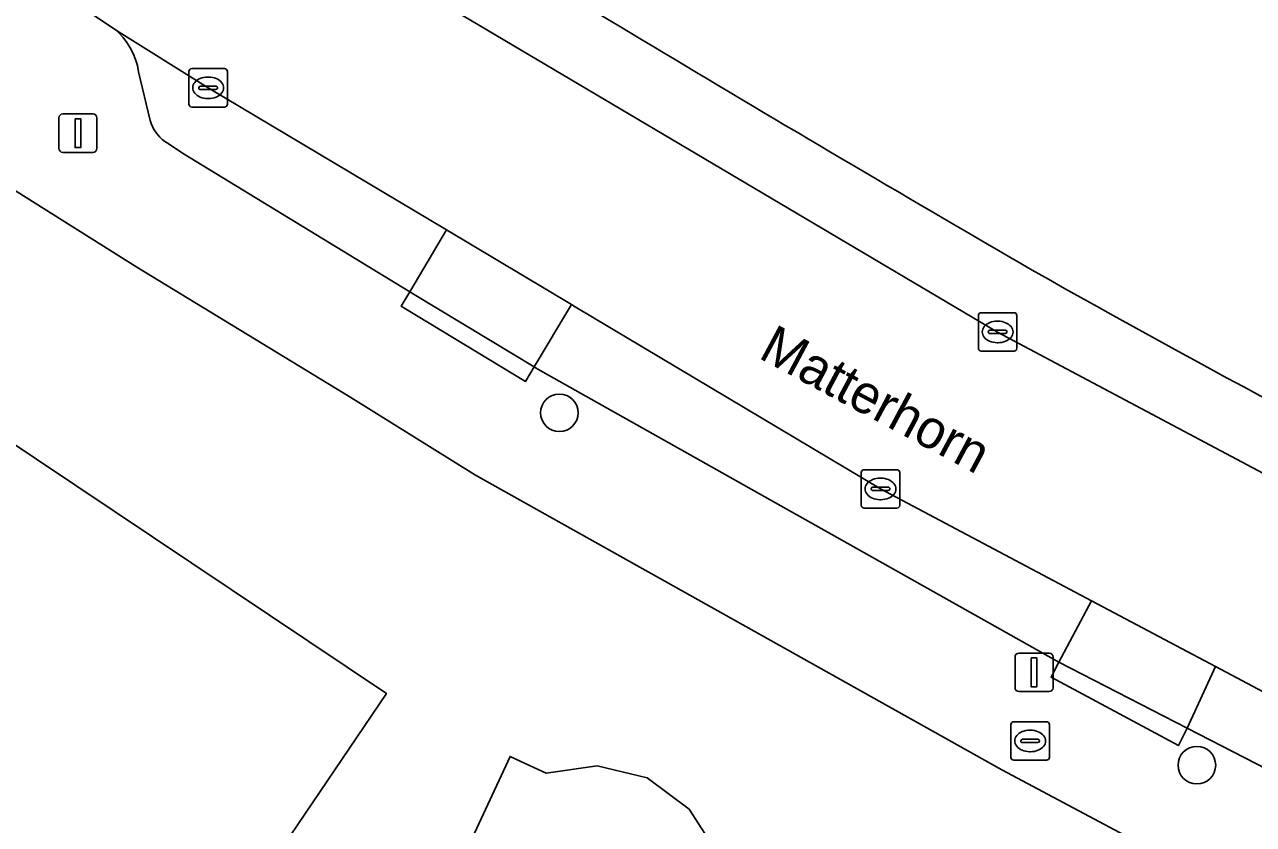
# Model space of a CAD drawing. Extents: x 158835 to 160077, y 386387 to 387778.
# Drawn here: x 159322.29 to 159354.26, y 386620.94 to 386641.75 of the extents above; entities that cross this region are included whole.
import ezdxf

# ---------------------------------------------------------------- set-up
doc = ezdxf.new("R2010")
doc.units = 0
for name, color, linetype in [('IMGEO_Boom', 7, 'Continuous'), ('IMGEO_Brandkraan', 7, 'Continuous'), ('IMGEO_Erf', 7, 'Continuous'), ('IMGEO_Kolk', 7, 'Continuous'), ('IMGEO_Lichtmast', 7, 'Continuous'), ('IMGEO_Openbare_ruimte_label', 7, 'Continuous'), ('IMGEO_Pand', 7, 'Continuous'), ('IMGEO_Parkeervlak_open', 7, 'Continuous'), ('IMGEO_Rijbaan_lokaal_gesloten', 7, 'Continuous'), ('IMGEO_Voetpad_open', 7, 'Continuous')]:
    doc.layers.add(name, color=color, linetype=linetype)

msp = doc.modelspace()

# ---------------------------------------------------------------- linework, layer by layer
at = {"layer": 'IMGEO_Boom'}
for centre in [(159336.201, 386631.65), (159352.786, 386622.485)]:
    msp.add_circle(centre, 0.489, dxfattribs=at)
at = {"layer": 'IMGEO_Brandkraan'}
for p, q in [((159347.947, 386622.688), (159347.947, 386623.54)), ((159348.022, 386623.614), (159348.874, 386623.614)), ((159348.948, 386623.54), (159348.948, 386622.688)), ((159348.206, 386623.108), (159348.206, 386623.12)), ((159348.249, 386623.157), (159348.647, 386623.157)), ((159348.435, 386623.394), (159348.46, 386623.394)), ((159348.69, 386623.12), (159348.69, 386623.108)), ((159348.644, 386623.071), (159348.246, 386623.071)), ((159348.458, 386622.834), (159348.433, 386622.834)), ((159348.874, 386622.614), (159348.022, 386622.614))]:
    msp.add_line(p, q, dxfattribs=at)
for points in [[(159347.947, 386622.688), (159347.947, 386623.54)], [(159348.022, 386623.614), (159348.874, 386623.614)], [(159348.948, 386623.54), (159348.948, 386622.688)], [(159348.874, 386622.614), (159348.022, 386622.614)]]:
    msp.add_lwpolyline(points, dxfattribs=at)
for centre, radius, start, end in [((159348.024, 386623.538), 0.0765, 91.552, 178.448), ((159348.024, 386623.538), 0.0765, 91.552, 178.448), ((159348.872, 386623.538), 0.0765, 1.552, 88.448), ((159348.872, 386623.538), 0.0765, 1.552, 88.448), ((159348.246, 386623.117), 0.0403, 85.8775, 175.7526), ((159348.651, 386623.119), 0.0386, 1.7309, 96.639), ((159348.243, 386623.107), 0.0366, 178.938, 274.7102), ((159348.647, 386623.114), 0.043, 264.8664, 352.4533), ((159348.024, 386622.69), 0.0765, 181.552, 268.448), ((159348.024, 386622.69), 0.0765, 181.552, 268.448), ((159348.872, 386622.69), 0.0765, 271.552, 358.448), ((159348.872, 386622.69), 0.0765, 271.552, 358.448)]:
    msp.add_arc(centre, radius, start, end, dxfattribs=at)
for centre, major_axis, ratio, start_param, end_param in [((159348.434, 386623.114), (-0.387, 0.002), 0.722429, 4.712389, 7.853982), ((159348.459, 386623.114), (-0.39, 0.002), 0.717154, 1.570796, 4.712389)]:
    msp.add_ellipse(centre, major_axis=major_axis, ratio=ratio, start_param=start_param, end_param=end_param, dxfattribs=at)
at = {"layer": 'IMGEO_Erf'}
for points in [[(159426.262, 386590.078), (159425.471, 386590.29), (159424.673, 386590.43), (159422.846, 386590.766), (159421.294, 386591.006), (159420.138, 386591.222), (159418.758, 386591.64), (159417.314, 386592.1), (159409.486, 386594.837), (159405.916, 386596.132), (159403.97, 386596.822), (159400.475, 386598.135), (159386.22, 386603.858), (159382.649, 386605.402), (159367.084, 386612.517), (159363.661, 386614.16), (159351.051, 386620.582), (159347.709, 386622.366), (159334.021, 386630.024), (159330.778, 386632.045), (159325.211, 386635.435), (159320.616, 386638.324)], [(159329.986, 386612.103), (159334.918, 386622.713), (159335.31, 386622.531), (159335.861, 386622.275), (159337.184, 386622.464), (159338.486, 386622.151), (159339.578, 386621.338), (159340.316, 386620.2)]]:
    msp.add_lwpolyline(points, dxfattribs=at)
msp.add_lwpolyline([(159326.892, 386617.237), (159326.589, 386616.789), (159323.922, 386618.593), (159324.22, 386619.033), (159321.202, 386621.061), (159313.402, 386609.64), (159309.341, 386611.541), (159309.249, 386611.591), (159310.962, 386614.093), (159310.479, 386614.408), (159312.402, 386617.249), (159311.925, 386617.552), (159313.862, 386620.39), (159313.389, 386620.699), (159315.32, 386623.54), (159314.84, 386623.851), (159316.431, 386626.201), (159316.933, 386626.939), (159317.487, 386626.563), (159318.424, 386627.943), (159317.106, 386628.824), (159317.252, 386629.043), (159319.546, 386632.48), (159331.703, 386624.349)], close=True, dxfattribs=at)
for centre, radius, start, end in [((159790.309, 387395.826), 879.49, 238.436929, 239.84473), ((159511.952, 386925.067), 332.636, 240.56851, 243.23292)]:
    msp.add_arc(centre, radius, start, end, dxfattribs=at)
at = {"layer": 'IMGEO_Kolk'}
for p, q in [((159326.563, 386639.677), (159326.563, 386640.529)), ((159326.638, 386640.603), (159327.49, 386640.603)), ((159327.051, 386640.383), (159327.076, 386640.383)), ((159327.564, 386640.529), (159327.564, 386639.677)), ((159326.822, 386640.097), (159326.822, 386640.109)), ((159327.26, 386640.06), (159326.862, 386640.06)), ((159326.865, 386640.146), (159327.263, 386640.146)), ((159327.306, 386640.109), (159327.306, 386640.097)), ((159327.074, 386639.823), (159327.049, 386639.823)), ((159327.49, 386639.603), (159326.638, 386639.603)), ((159347.101, 386633.327), (159347.101, 386634.179)), ((159347.176, 386634.253), (159348.028, 386634.253)), ((159347.589, 386634.033), (159347.614, 386634.033)), ((159348.102, 386634.179), (159348.102, 386633.327)), ((159347.36, 386633.747), (159347.36, 386633.759)), ((159347.798, 386633.71), (159347.4, 386633.71)), ((159347.403, 386633.796), (159347.801, 386633.796)), ((159347.844, 386633.759), (159347.844, 386633.747)), ((159347.612, 386633.473), (159347.587, 386633.473)), ((159348.028, 386633.253), (159347.176, 386633.253)), ((159344.13, 386630.17), (159344.982, 386630.17)), ((159344.055, 386629.244), (159344.055, 386630.096)), ((159344.543, 386629.95), (159344.568, 386629.95)), ((159345.056, 386630.096), (159345.056, 386629.244)), ((159344.314, 386629.664), (159344.314, 386629.676)), ((159344.752, 386629.627), (159344.354, 386629.627)), ((159344.357, 386629.713), (159344.755, 386629.713)), ((159344.798, 386629.676), (159344.798, 386629.664)), ((159344.566, 386629.39), (159344.541, 386629.39)), ((159344.982, 386629.17), (159344.13, 386629.17))]:
    msp.add_line(p, q, dxfattribs=at)
for points in [[(159326.563, 386639.677), (159326.563, 386640.529)], [(159326.638, 386640.603), (159327.49, 386640.603)], [(159327.564, 386640.529), (159327.564, 386639.677)], [(159327.49, 386639.603), (159326.638, 386639.603)], [(159347.101, 386633.327), (159347.101, 386634.179)], [(159347.176, 386634.253), (159348.028, 386634.253)], [(159348.102, 386634.179), (159348.102, 386633.327)], [(159348.028, 386633.253), (159347.176, 386633.253)], [(159344.13, 386630.17), (159344.982, 386630.17)], [(159344.055, 386629.244), (159344.055, 386630.096)], [(159345.056, 386630.096), (159345.056, 386629.244)], [(159344.982, 386629.17), (159344.13, 386629.17)]]:
    msp.add_lwpolyline(points, dxfattribs=at)
for centre, radius, start, end in [((159326.64, 386640.527), 0.0765, 91.552, 178.448), ((159326.64, 386640.527), 0.0765, 91.552, 178.448), ((159327.488, 386640.527), 0.0765, 1.552, 88.448), ((159327.488, 386640.527), 0.0765, 1.552, 88.448), ((159326.862, 386640.106), 0.0403, 85.8775, 175.7526), ((159326.859, 386640.096), 0.0366, 178.938, 274.7102), ((159327.263, 386640.103), 0.043, 264.8664, 352.4533), ((159327.267, 386640.108), 0.0386, 1.7309, 96.639), ((159326.64, 386639.679), 0.0765, 181.552, 268.448), ((159326.64, 386639.679), 0.0765, 181.552, 268.448), ((159327.488, 386639.679), 0.0765, 271.552, 358.448), ((159327.488, 386639.679), 0.0765, 271.552, 358.448), ((159347.178, 386634.177), 0.0765, 91.552, 178.448), ((159347.178, 386634.177), 0.0765, 91.552, 178.448), ((159348.026, 386634.177), 0.0765, 1.552, 88.448), ((159348.026, 386634.177), 0.0765, 1.552, 88.448), ((159347.4, 386633.756), 0.0403, 85.8775, 175.7526), ((159347.397, 386633.746), 0.0366, 178.938, 274.7102), ((159347.801, 386633.753), 0.043, 264.8664, 352.4533), ((159347.805, 386633.758), 0.0386, 1.7309, 96.639), ((159347.178, 386633.329), 0.0765, 181.552, 268.448), ((159347.178, 386633.329), 0.0765, 181.552, 268.448), ((159348.026, 386633.329), 0.0765, 271.552, 358.448), ((159348.026, 386633.329), 0.0765, 271.552, 358.448), ((159344.132, 386630.094), 0.0765, 91.552, 178.448), ((159344.132, 386630.094), 0.0765, 91.552, 178.448), ((159344.98, 386630.094), 0.0765, 1.552, 88.448), ((159344.98, 386630.094), 0.0765, 1.552, 88.448), ((159344.354, 386629.673), 0.0403, 85.8775, 175.7526), ((159344.351, 386629.663), 0.0366, 178.938, 274.7102), ((159344.755, 386629.67), 0.043, 264.8664, 352.4533), ((159344.759, 386629.675), 0.0386, 1.7309, 96.639), ((159344.132, 386629.246), 0.0765, 181.552, 268.448), ((159344.132, 386629.246), 0.0765, 181.552, 268.448), ((159344.98, 386629.246), 0.0765, 271.552, 358.448), ((159344.98, 386629.246), 0.0765, 271.552, 358.448)]:
    msp.add_arc(centre, radius, start, end, dxfattribs=at)
for centre, major_axis, ratio, start_param, end_param in [((159327.05, 386640.103), (-0.387, 0.002), 0.722429, 4.712389, 7.853982), ((159327.075, 386640.103), (-0.39, 0.002), 0.717154, 1.570796, 4.712389), ((159347.588, 386633.753), (-0.387, 0.002), 0.722429, 4.712389, 7.853982), ((159347.613, 386633.753), (-0.39, 0.002), 0.717154, 1.570796, 4.712389), ((159344.542, 386629.67), (-0.387, 0.002), 0.722429, 4.712389, 7.853982), ((159344.567, 386629.67), (-0.39, 0.002), 0.717154, 1.570796, 4.712389)]:
    msp.add_ellipse(centre, major_axis=major_axis, ratio=ratio, start_param=start_param, end_param=end_param, dxfattribs=at)
at = {"layer": 'IMGEO_Lichtmast'}
for p, q in [((159323.281, 386639.425), (159324.071, 386639.425)), ((159324.071, 386639.425), (159323.281, 386639.425)), ((159323.181, 386638.525), (159323.181, 386639.325)), ((159323.181, 386639.325), (159323.181, 386638.525)), ((159324.171, 386639.325), (159324.171, 386638.525)), ((159324.171, 386638.525), (159324.171, 386639.325)), ((159324.071, 386638.425), (159323.281, 386638.425)), ((159323.281, 386638.425), (159324.071, 386638.425)), ((159348.154, 386625.398), (159348.944, 386625.398)), ((159348.944, 386625.398), (159348.154, 386625.398)), ((159348.054, 386624.498), (159348.054, 386625.298)), ((159348.054, 386625.298), (159348.054, 386624.498)), ((159349.044, 386625.298), (159349.044, 386624.498)), ((159349.044, 386624.498), (159349.044, 386625.298)), ((159348.944, 386624.398), (159348.154, 386624.398)), ((159348.154, 386624.398), (159348.944, 386624.398))]:
    msp.add_line(p, q, dxfattribs=at)
for points in [[(159323.601, 386639.3), (159323.751, 386639.3), (159323.751, 386638.55), (159323.601, 386638.55), (159323.601, 386639.3)], [(159348.474, 386625.273), (159348.624, 386625.273), (159348.624, 386624.523), (159348.474, 386624.523), (159348.474, 386625.273)]]:
    msp.add_lwpolyline(points, dxfattribs=at)
for centre, start, end in [((159323.281, 386639.325), 90, 180), ((159323.281, 386639.325), 90, 180), ((159324.071, 386639.325), 0, 90), ((159324.071, 386639.325), 360, 90), ((159323.281, 386638.525), 180, 270), ((159323.281, 386638.525), 180, 270), ((159324.071, 386638.525), 270, 0), ((159324.071, 386638.525), 270, 0), ((159348.154, 386625.298), 90, 180), ((159348.154, 386625.298), 90, 180), ((159348.944, 386625.298), 0, 90), ((159348.944, 386625.298), 360, 90), ((159348.154, 386624.498), 180, 270), ((159348.154, 386624.498), 180, 270), ((159348.944, 386624.498), 270, 0), ((159348.944, 386624.498), 270, 0)]:
    msp.add_arc(centre, 0.1, start, end, dxfattribs=at)
at = {"layer": 'IMGEO_Pand'}
msp.add_lwpolyline([(159331.703, 386624.349), (159319.546, 386632.48), (159317.252, 386629.043), (159317.106, 386628.824), (159318.424, 386627.943), (159317.487, 386626.563), (159316.933, 386626.939), (159316.431, 386626.201), (159314.84, 386623.851), (159315.32, 386623.54), (159313.389, 386620.699), (159313.862, 386620.39), (159311.925, 386617.552), (159312.402, 386617.249), (159310.479, 386614.408), (159310.962, 386614.093), (159309.249, 386611.591), (159309.341, 386611.541), (159313.402, 386609.64), (159321.202, 386621.061), (159324.22, 386619.033), (159323.922, 386618.593), (159326.589, 386616.789), (159326.892, 386617.237)], close=True, dxfattribs=at)
msp.add_lwpolyline([(159340.316, 386620.2), (159339.578, 386621.338), (159338.486, 386622.151), (159337.184, 386622.464), (159335.861, 386622.275), (159335.31, 386622.531), (159334.918, 386622.713), (159329.986, 386612.103)], dxfattribs=at)
at = {"layer": 'IMGEO_Parkeervlak_open'}
for points in [[(159333.267, 386636.405), (159327.065, 386640.104), (159324.681, 386641.593), (159324.74, 386641.536), (159324.851, 386641.414), (159324.951, 386641.282), (159325.039, 386641.142), (159325.114, 386640.995), (159325.175, 386640.841), (159325.223, 386640.683), (159325.256, 386640.521), (159325.558, 386639.257), (159325.583, 386639.175), (159325.615, 386639.096), (159325.654, 386639.019), (159325.699, 386638.947), (159325.751, 386638.879), (159325.809, 386638.816), (159325.872, 386638.758), (159325.94, 386638.706), (159326.013, 386638.661), (159326.023, 386638.655), (159326.401, 386638.4), (159332.308, 386634.797)], [(159336.517, 386634.466), (159335.549, 386632.842), (159335.645, 386632.784), (159349.197, 386625.162), (159350.044, 386626.76), (159344.556, 386629.671), (159336.613, 386634.409)], [(159358.412, 386622.321), (159353.27, 386625.049), (159352.531, 386623.447), (159365.054, 386617.003), (159365.882, 386618.722)]]:
    msp.add_lwpolyline(points, close=True, dxfattribs=at)
at = {"layer": 'IMGEO_Rijbaan_lokaal_gesloten'}
msp.add_lwpolyline([(159361.292, 386626.474), (159347.601, 386633.751), (159329.982, 386644.184), (159325.765, 386646.95), (159323.991, 386648.114), (159320.24, 386650.892), (159314.969, 386655.443), (159311.528, 386651.956), (159311.772, 386651.715), (159313.292, 386650.328), (159314.004, 386649.679), (159320.182, 386644.697), (159321.779, 386643.55), (159324.681, 386641.593), (159327.065, 386640.104), (159333.267, 386636.405), (159336.517, 386634.466), (159336.613, 386634.409), (159344.556, 386629.671), (159350.044, 386626.76), (159353.27, 386625.049), (159358.412, 386622.321)], dxfattribs=at)
at = {"layer": 'IMGEO_Voetpad_open'}
for points in [[(159329.951, 386646.444), (159329.93, 386646.438), (159323.753, 386651.584), (159321.688, 386653.27), (159320.928, 386651.751), (159324.646, 386648.998), (159323.991, 386648.114), (159325.765, 386646.95), (159329.982, 386644.184), (159347.601, 386633.751), (159361.292, 386626.474)], [(159310.426, 386652.211), (159307.024, 386649.266), (159308.202, 386647.929), (159313.534, 386644.225), (159315.608, 386642.634), (159317.618, 386641.092), (159320.616, 386638.324), (159325.211, 386635.435), (159330.778, 386632.045), (159334.021, 386630.024), (159347.709, 386622.366), (159351.051, 386620.582), (159363.661, 386614.16)], [(159326.401, 386638.4), (159326.023, 386638.655), (159326.013, 386638.661), (159325.94, 386638.706), (159325.872, 386638.758), (159325.809, 386638.816), (159325.751, 386638.879), (159325.699, 386638.947), (159325.654, 386639.019), (159325.615, 386639.096), (159325.583, 386639.175), (159325.558, 386639.257), (159325.256, 386640.521), (159325.223, 386640.683), (159325.175, 386640.841), (159325.114, 386640.995), (159325.039, 386641.142), (159324.951, 386641.282), (159324.851, 386641.414), (159324.74, 386641.536), (159324.681, 386641.593), (159321.779, 386643.55)], [(159365.054, 386617.003), (159352.531, 386623.447), (159352.307, 386622.992), (159348.992, 386624.772), (159349.197, 386625.162), (159335.645, 386632.784), (159335.549, 386632.842), (159335.322, 386632.466), (159332.199, 386634.358), (159332.085, 386634.427), (159332.308, 386634.797), (159326.401, 386638.4)]]:
    msp.add_lwpolyline(points, dxfattribs=at)
for points in [[(159333.267, 386636.405), (159332.308, 386634.797), (159332.422, 386634.727), (159335.549, 386632.842), (159336.517, 386634.466)], [(159332.422, 386634.727), (159332.308, 386634.797), (159332.085, 386634.427), (159332.199, 386634.358), (159335.322, 386632.466), (159335.549, 386632.842)], [(159353.27, 386625.049), (159350.044, 386626.76), (159349.197, 386625.162), (159352.531, 386623.447)], [(159352.531, 386623.447), (159349.197, 386625.162), (159348.992, 386624.772), (159352.307, 386622.992)]]:
    msp.add_lwpolyline(points, close=True, dxfattribs=at)
for centre, radius, start, end in [((159790.309, 387395.826), 879.49, 238.436929, 239.84473), ((159511.952, 386925.067), 332.636, 240.56851, 243.23292)]:
    msp.add_arc(centre, radius, start, end, dxfattribs=at)

# ---------------------------------------------------------------- texts
at = {"layer": 'IMGEO_Openbare_ruimte_label'}
msp.add_text('Matterhorn', height=1, rotation=331.8467, dxfattribs=at).set_placement((159341.35, 386633.092))

doc.saveas('drawing.dxf')
